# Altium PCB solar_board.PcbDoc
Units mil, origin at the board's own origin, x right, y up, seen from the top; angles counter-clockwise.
Board outline 7810 x 5890 mil, 2 copper layers (Top Layer, Bottom Layer); 87 components, 116 nets, 371 pads, 113 vias.
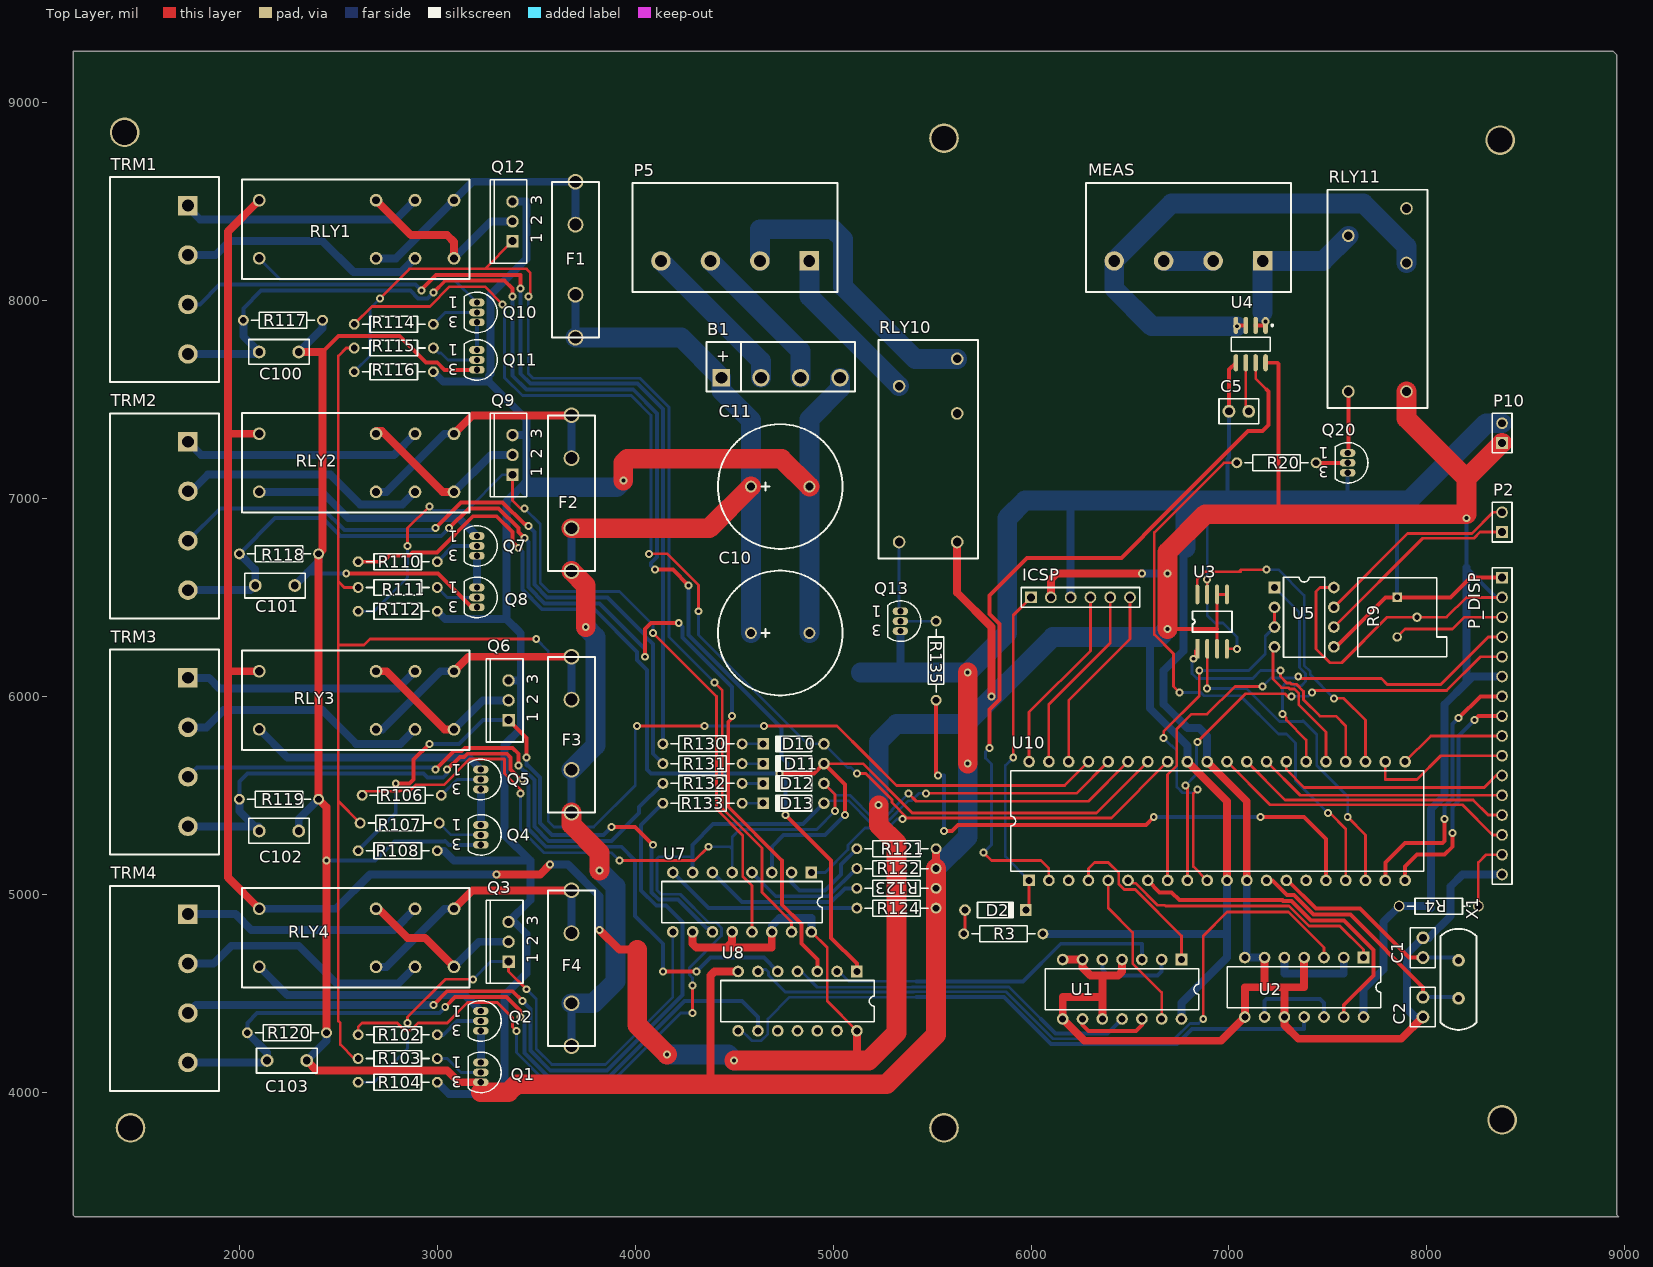
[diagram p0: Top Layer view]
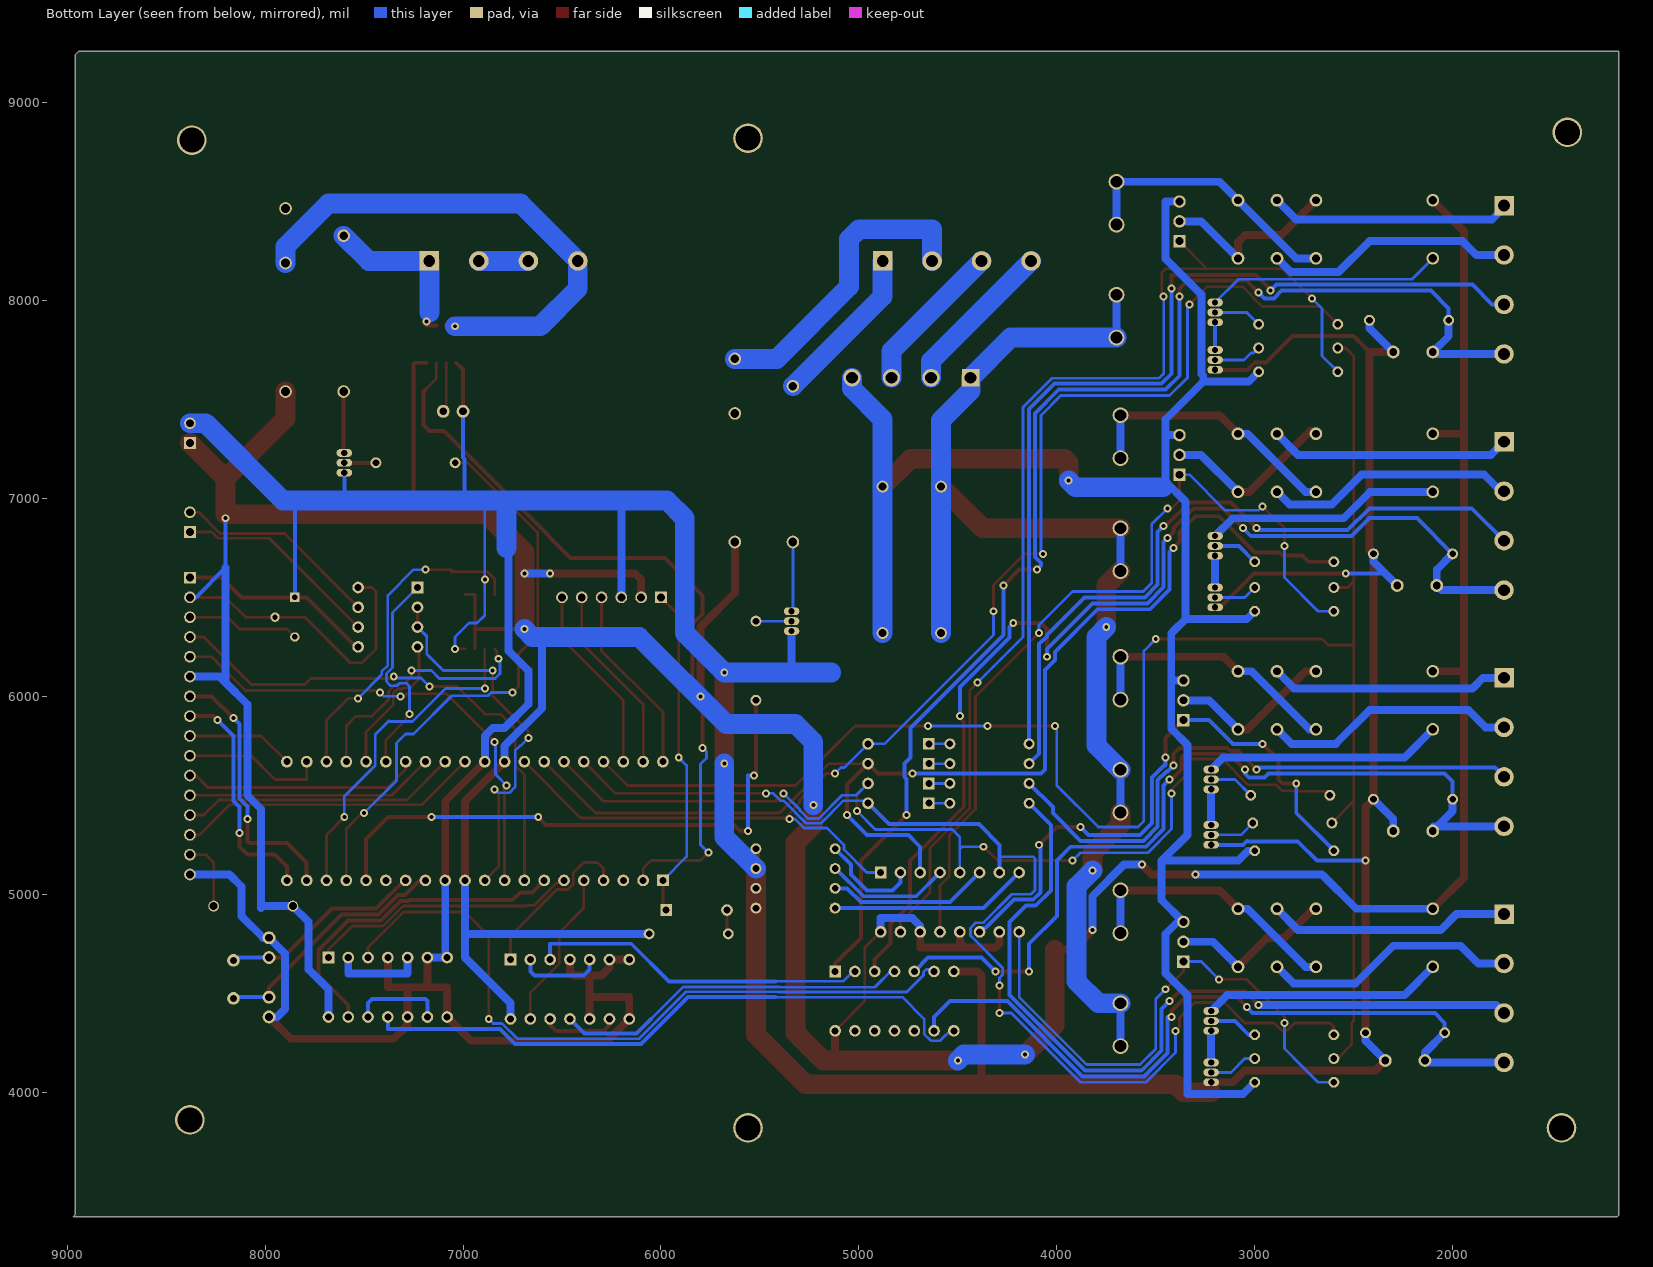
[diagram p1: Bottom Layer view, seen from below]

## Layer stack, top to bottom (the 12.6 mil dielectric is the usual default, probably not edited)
Top Layer: signal copper 1.4
Dielectric: dielectric 12.6, FR-4, Dk 4.8
Bottom Layer: signal copper 1.4

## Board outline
1160,3490 1160,9260 8940,9260 8960,9240 8960,3380 8970,3370 1170,3370 1160,3380

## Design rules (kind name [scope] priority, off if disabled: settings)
Clearance [All] p1: gap=10
ComponentClearance [All] p1: gap=10 collisioncheckmode=3 verticalgap=10
PolygonConnect [All] p1: connectstyle=Relief reliefconductorwidth=10 reliefentries=4 polygonreliefangle="90 Angle"
RoutingCorners [All] p1: cornerstyle=45-Degree minsetback=20 maxsetback=20
RoutingPriority [InNet('GND')] p1: routingpriority=0
RoutingVias [All] p1: holewidth=20 width=40 viastyle="Through Hole" minholewidth=20 minwidth=40 maxholewidth=20 maxwidth=40
SolderMaskExpansion [All] p1: expansion=4
TestPointUsage [All] p1: valid=0 allowmultiple=FALSE
Testpoint [All] p1: side=3 testpointundercomponent=TRUE minsize=40 maxsize=100 preferedsize=60 minholesize=0 maxholesize=40 preferedholesize=32 testpointgrid=1 style=297 order=0123456789
Width [All] p1: maxlimit=100 minlimit=10 preferedwidth=14
16 further rules are at their usual default settings.

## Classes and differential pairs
component class MTR_DRV1: B1 C10 C11 C100 C101 C102 C103 D10 D11 D12 D13 F1 F2 F3 F4 P5 Q1 Q2 Q3 Q4 Q5 Q6 Q7 Q8 Q9 Q10 Q11 Q12 Q13 R102 R103 R104 R106 R107 R108 R110 R111 R112 R114 R115 R116 R117 R118 R119 R120 R121 R122 R123 R124 R130 R131 R132 R133 R135 RLY1 RLY2 RLY3 RLY4 RLY10 TRM1 TRM2 TRM3 TRM4 U7 »»»
component class main: C1 C2 C5 D2 ICSP MEAS P2 P10 P_DISP Q20 R3 R4 R9 R20 RLY9 RLY11 U3 U4 U5 U10 U? X1
component class "Sensor frontend": U1 U2 U8

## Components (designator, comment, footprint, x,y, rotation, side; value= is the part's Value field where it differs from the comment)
B1 "BRIDGE" BRIDGE 4360,7540 r0 top
C1 "Cap" VP32-3.2 7980,4730 r270 top
C2 "Cap" VP32-3.2 7980,4430 r90 top
C5 "Cap" VP32-3.2 7050,7440 r0 top
C10 "Cap Pol1" Capacitor2200u50v 4880,6320 r180 top
C11 "Cap Pol1" Capacitor2200u50v 4880,7060 r180 top
C100 "Cap" VP45-3.2 2200,7740 r180 top
C101 "Cap" VP45-3.2 2180,6560 r180 top
C102 "Cap" VP45-3.2 2200,5320 r180 top
C103 "Cap" VP45-3.2 2240,4160 r180 top
D2 "Diode 1N4150" DO-35A 5820,4920 r0 top
D10 "Diode 1N4150" DO-35A 4800,5760 r180 top
D11 "Diode 1N4150" DO-35A 4800,5660 r180 top
D12 "Diode 1N4150" DO-35A 4800,5560 r180 top
D13 "Diode 1N4150" DO-35A 4800,5460 r180 top
F1 "Fuse5mm" Fuse5mm 3580,8600 r270 top
F2 "Fuse5mm" Fuse5mm 3560,7420 r270 top
F3 "Fuse5mm" Fuse5mm 3560,6200 r270 top
F4 "Fuse5mm" Fuse5mm 3560,5020 r270 top
ICSP "Header 6" HDR1X6 6000,6500 r0 top
MEAS "4XTERMINAL" BLK_TERMX4 7170,8200 r180 top
P2 "Header 2" HDR1X2 8380,6830 r90 top
P5 "4XTERMINAL" BLK_TERMX4 4880,8200 r180 top
P10 "Header 2" HDR1X2 8380,7280 r90 top
P_DISP "Header 16" HDR1X16 8380,6600 r270 top
Q1 "P2N2222A" 29-04 3220,4100 r180 top
Q2 "P2N2222A" 29-04 3220,4360 r180 top
Q3 "IRF3205" TO-220AB 3360,4760 r90 top
Q4 "P2N2222A" 29-04 3220,5300 r180 top
Q5 "P2N2222A" 29-04 3220,5580 r180 top
Q6 "IRF3205" TO-220AB 3360,5980 r90 top
Q7 "P2N2222A" 29-04 3200,6760 r180 top
Q8 "P2N2222A" 29-04 3200,6500 r180 top
Q9 "IRF3205" TO-220AB 3380,7220 r90 top
Q10 "P2N2222A" 29-04 3200,7940 r180 top
Q11 "P2N2222A" 29-04 3200,7700 r180 top
Q12 "IRF3205" TO-220AB 3380,8400 r90 top
Q13 "P2N2222A" 29-04 5340,6380 r180 top
Q20 "P2N2222A" 29-04 7600,7180 r180 top
R3 "Res1" AXIAL-0.4#1 5860,4800 r0 top
R4 "Res1" AXIAL-0.4#2 8060,4940 r180 top
R9 "Res Tap" VR4 7900,6400 r270 top
R20 "Res1" AXIAL-0.4#1 7240,7180 r180 top
R102 "Res1" AXIAL-0.4#1 2800,4290 r180 top
R103 "Res1" AXIAL-0.4#1 2800,4170 r180 top
R104 "Res1" AXIAL-0.4#1 2800,4050 r180 top
R106 "Res1" AXIAL-0.4#1 2820,5500 r180 top
R107 "Res1" AXIAL-0.4#1 2810,5360 r180 top
R108 "Res1" AXIAL-0.4#1 2800,5220 r180 top
R110 "Res1" AXIAL-0.4#1 2800,6680 r180 top
R111 "Res1" AXIAL-0.4#1 2800,6550 r180 top
R112 "Res1" AXIAL-0.4#1 2800,6430 r180 top
R114 "Res1" AXIAL-0.4#1 2780,7880 r180 top
R115 "Res1" AXIAL-0.4#1 2780,7760 r180 top
R116 "Res1" AXIAL-0.4#1 2780,7640 r180 top
R117 "Res1" AXIAL-0.4#1 2220,7900 r180 top
R118 "Res1" AXIAL-0.4#1 2200,6720 r180 top
R119 "Res1" AXIAL-0.4#1 2200,5480 r180 top
R120 "Res1" AXIAL-0.4#1 2240,4300 r180 top
R121 "Res1" AXIAL-0.4#1 5320,5230 r180 top
R122 "Res1" AXIAL-0.4#1 5320,5130 r180 top
R123 "Res1" AXIAL-0.4#1 5320,5030 r180 top
R124 "Res1" AXIAL-0.4#1 5320,4930 r180 top
R130 "Res1" AXIAL-0.4#1 4340,5760 r180 top
R131 "Res1" AXIAL-0.4#1 4340,5660 r180 top
R132 "Res1" AXIAL-0.4#1 4340,5560 r180 top
R133 "Res1" AXIAL-0.4#1 4340,5460 r180 top
R135 "Res1" AXIAL-0.4#1 5520,6180 r90 top
RLY1 "RELAY2" DPDT_Relay 2100,8360 r180 top
RLY2 "RELAY2" DPDT_Relay 2100,7180 r180 top
RLY3 "RELAY2" DPDT_Relay 2100,5980 r180 top
RLY4 "RELAY2" DPDT_Relay 2100,4780 r180 top
RLY10 "RELAY1" SPDT 5480,6780 r270 top
RLY11 "RELAY1" SPDT 7750,7540 r270 top
TRM1 "4XTERMINAL" BLK_TERMX4 1740,8480 r270 top
TRM2 "4XTERMINAL" BLK_TERMX4 1740,7286.67 r270 top
TRM3 "4XTERMINAL" BLK_TERMX4 1740,6093.33 r270 top
TRM4 "4XTERMINAL" BLK_TERMX4 1740,4900 r270 top
U1 "CD4013BCN" N14A 6460,4520 r180 top
U2 "CD4013BCN" N14A 7380,4530 r180 top
U3 "AT45DB161" SOP8 6840,6240 r90 top
U4 "ACS712" 751-05_N 7110,7780 r270 top
U5 "MAX485EPA" PA8 7380,6400 r270 top
U7 "ILD74" J016D 4540,4960 r180 top
U8 "MC74HC14AN" 646-06 4820,4460 r180 top
U10 "PIC18F458-E/P" PDIP600-40 6940,5370 r0 top
X1 "XTAL" XTAL 8160,4570 r90 top

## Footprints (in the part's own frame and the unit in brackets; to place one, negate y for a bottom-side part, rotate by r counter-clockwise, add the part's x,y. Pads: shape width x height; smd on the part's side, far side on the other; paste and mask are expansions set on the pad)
29-04 [mm] "TO, Flat Index; 3 In-Line, Axial Leads; Body Dia. 4.8mm; Leads 0.48 x 0.5 mm (max)"
  oval 2x1 hole 0.8: 1(0,-1.27) 2(0,0) 3(0,1.27)
  silkscreen extent -2.6,-2.6 1.6,2.6
646-06 [mm] "DIP; 14 Leads; Row Spacing 7.62 mm; Pitch 2.54 mm"
  rect 1.5x1.5 hole 0.9: 1(-7.62,-3.81)
  round 1.5 hole 0.9: 2(-5.08,-3.81) 3(-2.54,-3.81) 4(0,-3.81) 5(2.54,-3.81) 6(5.08,-3.81) 7(7.62,-3.81) 8(7.62,3.81) 9(5.08,3.81) 10(2.54,3.81) 11(0,3.81) 12(-2.54,3.81) 13(-5.08,3.81) 14(-7.62,3.81)
  silkscreen extent -9.85,-2.65 9.85,2.65
751-05_N [mm] "SOIC, 8-Leads, Body 4.9x3.9mm, Pitch 1.27mm, IPC Medium Density"
  oval 2.2x0.6 smd: 1(-2.4,1.905) 2(-2.4,0.635) 3(-2.4,-0.635) 4(-2.4,-1.905) 5(2.4,-1.905) 6(2.4,-0.635) 7(2.4,0.635) 8(2.4,1.905)
  silkscreen extent -2.52,-2.5 0.9,2.88, body extent -2,-2.5 2,2.5, height 1.75
AXIAL-0.4#1 [mm] "Resistor; 2 Leads"
  round 1.4 hole 0.85: 1(-5.08,0) 2(5.08,0)
  silkscreen extent -4.06,-1.02 4.06,1.02
AXIAL-0.4#2 [mm] "Resistor; 2 Leads"
  round 1.4 hole 1.016: 1(-5.08,0) 2(5.08,0)
  silkscreen extent -4.06,-1.02 4.06,1.02
BLK_TERMX4 [mm] "4 PIN BLOCK TERMINCAL (6.35MM PITCH)"
  rect 2.5x2.5 hole 1.5: 0(0,0)
  round 2.5 hole 1.5: 1(6.35,0) 2(12.7,0) 3(19.05,0)
  silkscreen extent -3.63,-10 22.68,4
BRIDGE [mil] "KBL401"
  rect 88x88 hole 60: 1(75,70)
  round 88 hole 60: 2(275,70) 3(475,70) 4(675,70)
  silkscreen extent 0,0 750,250
Capacitor2200u50v [mil]
  round 60 hole 40: 1(295.28,0) 2(0,0)
  silkscreen extent -167,-315 463,315
DO-35A [mm] "Diode, Axial; Body 4.6 x 1.9 mm (LxDia. max), Lead Dia. 0.53 mm (max)"
  round 1.5 hole 0.9: 1(-3.9,0)
  rect 1.5x1.5 hole 0.9: 2(3.9,0)
  silkscreen extent -2.3,-1 2.4,1
DPDT_Relay [mm]
  round 1.626 hole 1.016: 1(-25,3.725) 2(-20,3.725) 3(-15,3.725) 6(-15,-3.725) 7(-20,-3.725) 8(-25,-3.725)
  round 1.626 hole 1.118: 4(0,3.725) 5(0,-3.725)
  silkscreen extent -27,-6.4 2.2,6.4
Fuse5mm [mil]
  round 80 hole 60: 1(0,118.11) 2(216.54,118.11) 3(570.87,118.11) 4(787.4,118.11)
  silkscreen extent 0,0 787,236
HDR1X2 [mm] "Connector; Header; 2 Position"
  rect 1.5x1.5 hole 1.016: 1(0,0)
  round 1.5 hole 1.016: 2(2.54,0)
  silkscreen extent -1.27,-1.27 3.81,1.27
HDR1X6 [mm] "Connector; Header; 6 Position"
  rect 1.5x1.5 hole 1.016: 1(0,0)
  round 1.5 hole 1.016: 2(2.54,0) 3(5.08,0) 4(7.62,0) 5(10.16,0) 6(12.7,0)
  silkscreen extent -1.27,-1.27 13.97,1.27
HDR1X16 [mm] "Connector; Header; 16 Position"
  rect 1.5x1.5 hole 1.016: 1(0,0)
  round 1.5 hole 1.016: 2(2.54,0) 3(5.08,0) 4(7.62,0) 5(10.16,0) 6(12.7,0) 7(15.24,0) 8(17.78,0) 9(20.32,0) 10(22.86,0) 11(25.4,0) 12(27.94,0) 13(30.48,0) 14(33.02,0) 15(35.56,0) 16(38.1,0)
  silkscreen extent -1.27,-1.27 39.37,1.27
J016D [mm] "DIP; 16 Leads; Row Spacing 7.62 mm; Pitch 2.54 mm"
  rect 1.5x1.5 hole 0.9: 1(-8.89,-3.81)
  round 1.5 hole 0.9: 2(-6.35,-3.81) 3(-3.81,-3.81) 4(-1.27,-3.81) 5(1.27,-3.81) 6(3.81,-3.81) 7(6.35,-3.81) 8(8.89,-3.81) 9(8.89,3.81) 10(6.35,3.81) 11(3.81,3.81) 12(1.27,3.81) 13(-1.27,3.81) 14(-3.81,3.81) 15(-6.35,3.81) 16(-8.89,3.81)
  silkscreen extent -10.3,-2.65 10.3,2.65
N14A [mm] "DIP; 14 Leads; Row Spacing 7.62 mm; Pitch 2.54 mm"
  rect 1.5x1.5 hole 0.9: 1(-7.62,-3.81)
  round 1.5 hole 0.9: 2(-5.08,-3.81) 3(-2.54,-3.81) 4(0,-3.81) 5(2.54,-3.81) 6(5.08,-3.81) 7(7.62,-3.81) 8(7.62,3.81) 9(5.08,3.81) 10(2.54,3.81) 11(0,3.81) 12(-2.54,3.81) 13(-5.08,3.81) 14(-7.62,3.81)
  silkscreen extent -9.85,-2.65 9.85,2.65
PA8 [mm] "DIP; 8 Leads; Row Spacing 7.62 mm; Pitch 2.54 mm"
  rect 1.5x1.5 hole 0.9: 1(-3.81,-3.81)
  round 1.5 hole 0.9: 2(-1.27,-3.81) 3(1.27,-3.81) 4(3.81,-3.81) 5(3.81,3.81) 6(1.27,3.81) 7(-1.27,3.81) 8(-3.81,3.81)
  silkscreen extent -5.15,-2.65 5.15,2.65
PDIP600-40 [mm] "DIP, Plastic; 40 Leads; Row Spacing 15.24 mm; Pitch 2.54 mm"
  rect 1.5x1.5 hole 0.9: 1(-24.13,-7.62)
  round 1.5 hole 0.9: 2(-21.59,-7.62) 3(-19.05,-7.62) 4(-16.51,-7.62) 5(-13.97,-7.62) 6(-11.43,-7.62) 7(-8.89,-7.62) 8(-6.35,-7.62) 9(-3.81,-7.62) 10(-1.27,-7.62) 11(1.27,-7.62) 12(3.81,-7.62) 13(6.35,-7.62) 14(8.89,-7.62) 15(11.43,-7.62) 16(13.97,-7.62) 17(16.51,-7.62) 18(19.05,-7.62) 19(21.59,-7.62) 20(24.13,-7.62) 21(24.13,7.62) 22(21.59,7.62) 23(19.05,7.62) 24(16.51,7.62) 25(13.97,7.62) 26(11.43,7.62) 27(8.89,7.62) 28(6.35,7.62) 29(3.81,7.62) 30(1.27,7.62) 31(-1.27,7.62) 32(-3.81,7.62) 33(-6.35,7.62) 34(-8.89,7.62) 35(-11.43,7.62) 36(-13.97,7.62) 37(-16.51,7.62) 38(-19.05,7.62) 39(-21.59,7.62) 40(-24.13,7.62)
  silkscreen extent -26.5,-6.45 26.5,6.45
SOP8 [mil]
  rect 100x20 smd: 1(0,0)
  oval 100x20 smd: 2(0,-50) 3(0,-100) 4(0,-150) 5(275,-150) 6(275,-100) 7(275,-50) 8(275,0)
  silkscreen extent 85,-175 190,25
SPDT [mm] "1 From C relay"
  round 1.626 hole 1.118: 1(-20,-3.725) 2(0,3.725) 3(-23.5,3.725) 4(-16.5,3.725) 5(0,-3.725)
  silkscreen extent -25.9,-6.4 2.1,6.4
TO-220AB [mm] "TO, Thru-Hole, Vertical, Heatsink Mounted; 3 In-Line Leads; Pitch 2.54 mm"
  rect 1.6x1.6 hole 1: 1(-2.54,0)
  round 1.6 hole 1: 2(0,0) 3(2.54,0)
  silkscreen extent -5.35,-1.85 5.35,2.85
VP32-3.2 [mm] "Capacitor, Ceramic, Thru-Hole, Dipped Radial; Body 5.1 x 3.2 mm (WxT) Pin Spacing 2.54 mm (typ)"
  round 1.65 hole 1: 1(-1.27,0) 2(1.27,0)
  silkscreen extent -2.55,-1.6 2.55,1.6
VP45-3.2 [mm] "Capacitor, Ceramic, Thru-Hole, Dipped Radial; Body 7.8 x 3.2 mm (WxT) Pin Spacing 5.08 mm (typ)"
  round 1.65 hole 1: 1(-2.54,0) 2(2.54,0)
  silkscreen extent -3.9,-1.6 3.9,1.6
VR4 [mm] "Feed-Through Capacitor; 3 Leads"
  rect 1.2x1.2 hole 0.7: 1(-2.54,-1.27)
  round 1.2 hole 0.7: 2(0,1.27) 3(2.54,-1.27)
  silkscreen extent -5.08,-6.35 5.08,5.08
XTAL [mil]
  round 64.02 hole 35.98: 0(-96.06,0) 1(96.06,0)
  silkscreen extent -255,-92 255,92

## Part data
C1 C2 C5 C100 C101 C102 C103: "Capacitor"
C10 C11: "Polarized Capacitor (Radial)"
D2 D10 D11 D12 D13: "High Conductance Ultra Fast Diode"
ICSP: "Header, 6-Pin"
P2 P10: "Header, 2-Pin"
P_DISP: "Header, 16-Pin"
Q1 Q2 Q4 Q5 Q7 Q8 Q10 Q11 Q13 Q20: "Amplifier Transistor NPN Silicon"
Q3 Q6 Q9 Q12: "HEXFET Power MOSFET"
R3 R4 R20 R102 R103 R104 R106 R107 R108 R110 R111 R112 R114 R115 R116 R117 R118 R119 R120 R121 R122 R123 R124 R130 R131 R132 R133 R135: "Resistor"
R9: "Tapped Resistor"
U1 U2: "Dual D-Type Flip-Flop"
U5: "Low-Power, Slew-Rate-Limited RS-485/RS-422 Transceiver"
U7: "Optocoupler, Phototransistor Output, Dual Channel, TTL Compatible, Pb-free"
U8: "Hex Schmitt Trigger Inverter"
U10: "High Performance, Enhanced FLASH Microcontroller with CAN, 32K FLASH, 40-Pin PDIP, Standard Volt Range, Extended Temperature"

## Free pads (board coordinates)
  round 149.61 hole 125.98: 0(8380,3860) 1(8370,8810) 2(5560,8820) 3(5560,3820) 4(1450,3820) 5(1420,8850)

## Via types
v1: diameter 40, hole 20, Top Layer to Bottom Layer, 113 vias

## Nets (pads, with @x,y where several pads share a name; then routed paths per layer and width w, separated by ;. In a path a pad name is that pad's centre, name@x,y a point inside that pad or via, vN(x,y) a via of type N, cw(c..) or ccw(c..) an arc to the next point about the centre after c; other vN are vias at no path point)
GND: C1.1 C2.1 C5.1 C100.1 C101.1 C102.1 C103.1 ICSP.3 P10.2 P_DISP.1 P_DISP.16 Q1.3 Q4.3 Q8.3 Q11.3 Q13.3 Q20.3 R9.1 R117.1 R118.1 R119.1 R120.1 R121.1 R122.1 R123.1 R124.1 U1.4 U1.6 U1.7 U1.8 U1.10 U2.4 U2.6 U2.7 U2.8 U2.10 U3.4 U3.7 U4.5 U5.5 U8.7 U10.12 U10.31 | length 28897
  Top Layer w14: U3.7 v1(6890,6590) ; U3.4 v1(7040,6240)
  Top Layer w20: C103.1 2377.56,4122.44 ; 2420,7740 2500,7820 2810,7820 2942.44,7687.56 2999.7,7687.56 3037.26,7650 Q11.3 ; v1(2540,6620) 3004.19,6620 3174.19,6450 Q8.3 ; C5.1 7000,7650.51 U4.5 ; U5.5 7540,6250 7790,6500 R9.1 8120,6500 8220,6600 P_DISP.1
  Top Layer w40: C100.1 2420,7740 2420,6740 R118.1 R119.1 2440,5440 R120.1 ; C103.1 2390,4110 3050,4110 3110,4050 Q1.3 ; 4380,4040 4380,4590 4400,4610 U8.7 ; R124.1 R123.1 R122.1 R121.1 ; U1.7 U1.6 6260,4630 6300,4590 6360,4590 ; U1.10 6360,4480 ; U1.4 6460,4610 6440,4590 6360,4590 ; U10.31 7090,5470 U10.12 ; U2.6 7180,4530 ; U2.4 7380,4530 7280,4530 ; v1(7980,4380) 7870,4270 7350,4270 7280,4340 U2.10 7280,4530 ; 6360,4480 6160,4480 U1.8 6270,4260 6960,4260 U2.8 7080,4530 7180,4530 ; 6360,4480 6360,4590 ; 7180,4530 7280,4530
  Top Layer w100: 3220,4000 3360,4000 3400,4040 4380,4040 5270,4040 5520,4290 R124.1 R123.1 R122.1 ; v1(5680,5660) v1(5680,6120)
  Bottom Layer w14: 6880,6990 6890,6980 v1(6890,6590) 6890,6410 6930,6370 6970,6370 7040,6300 v1(7040,6240)
  Bottom Layer w20: 2345.15,6625.15 2350.31,6620 v1(2540,6620) ; v1(2440,5170) 2684.88,5170 2782.44,5267.56 3037.56,5267.56 3040,5270 3060,5250 Q4.3 ; C5.1 7000,7207.26 6992.44,7199.7 6992.44,7007.56 7010,6990 ; 7600,6990 Q20.3 ; R9.1 7850,6990
  Bottom Layer w40: C101.1 2345.15,6625.15 2400,6680 R118.1 ; C102.1 2300,5380 R119.1 ; C100.1 2420,7860 R117.1 ; C103.1 2440,4260 R120.1 ; Q11.3@3199.68,7650.31 Q11.3 ; 5340,6120 Q13.3 ; ICSP.3 6200,6990 ; 6780,6750 6770,6740 6770,6230 6670,6130 6670,5960 6790,5840 6850,5840 6890,5800 U10.31 ; U10.12 7090,4690 U2.7 U2.6 ; v1(7980,4380) 7940,4380 7900,4420 7900,4700 C1.1 8010,4780 8120,4890 8120,5040 8180,5100 P_DISP.16
  Bottom Layer w100: 5140,6120 5340,6120 v1(5680,6120) 5880,6320 5880,6900 5970,6990 6200,6990 6780,6990 ; R122.1 5680,5290 v1(5680,5660) ; 6780,6750 6780,6990 ; P10.2 8300,7380 7910,6990 7850,6990 7600,6990 7010,6990 6880,6990 6780,6990
HVGND: B1.4 C10.2 C11.2 Q3.3 Q6.3 Q9.3 Q12.3 R104.1 R108.1 R112.1 R116.1 | length 9740.4
  Top Layer w100: v1(3940,7090) 3940,7180 3960,7200 4740,7200 C11.2
  Bottom Layer w40: R116.1 3030,7590 3260,7590 ; R104.1 3060,3990 3340,3990 3340,4490 3450,4600 3450,4800 3391.5,4858.5 3358.5,4858.5 Q3.3 3470,4970 3470,5170 ; R108.1 3033.43,5220 3083.43,5170 3470,5170 ; R112.1 3040,6390 3350,6390 ; Q6.3 3420,6080 ; Q9.3 3450,7320 ; Q12.3 3450,8500 3450,8210 3269.37,8029.37 3269.37,7629.42 3260,7620.05 3260,7590 ; 3415,6325 3350,6390 ; 3450,7330 3450,7320 ; 3260,7590 3450,7400 3450,7320 ; 3350,6390 3350,6984.58 3450,7084.58 3450,7320 ; 3350,6390 3421.5,6318.5 3421.5,5836.08 3340,5754.58 3340,5300 3470,5170
  Bottom Layer w100: 3463.92,7056.08 3906.08,7056.08 v1(3940,7090) ; C10.2 C11.2 4880,7400 5035,7555 B1.4
NetB1_2: B1.2 P5.3 | length 799.2
  Bottom Layer w100: P5.3 4635,7695 B1.2
NetB1_3: B1.3 P5.2 | length 778.5
  Bottom Layer w100: P5.2 4835,7745 B1.3
NetC1_2: C1.2 U10.14 X1.1 | length 1037.3
  Top Layer w20: U10.14 7296.98,5070 7439.98,4927 7663,4927 7910,4680 C1.2
  Bottom Layer w20: C1.2 8146.06,4680 X1.1
NetC2_2: C2.2 U10.13 X1.0 | length 1246.2
  Top Layer w20: U10.13 7219.96,5070 7292.96,4997 7327.55,4997 7427.55,4897 7613,4897 7980,4530 C2.2
  Bottom Layer w20: C2.2 8153.94,4480 X1.0
NetC5_2: C5.2 U4.6 | length 251.7
  Top Layer w14: U4.6 7085,7455 C5.2
NetC100_2: C100.2 R117.2 TRM1.3 U8.1 | length 6657.8
  Top Layer w20: v1(2980,8040) 3040,8100 3339.92,8100 3380,8059.92 v1(3380,8020) ; v1(4100,6640) 4190,6640 v1(4270,6560) ; v1(4760,5400) 4990,5170 4990,4780 5120,4650 U8.1
  Bottom Layer w20: R117.2 2020,7960 2110,8050 2863.43,8050 2903.43,8010 2950,8010 v1(2980,8040) ; v1(3380,8020) 3380,7620 3450,7550 3990,7550 4110,7430 4110,6703.43 4080,6673.43 4080,6660 v1(4100,6640) ; v1(4270,6560) 4270,6310 4740,5840 4740,5690 4770,5660 4770,5593.43 4760,5583.43 v1(4760,5400)
  Bottom Layer w40: TRM1.3 2090,7730 C100.2 2020,7820 R117.2
NetC101_2: C101.2 R118.2 TRM2.3 U8.3 | length 5630.7
  Top Layer w20: v1(3060,6850) 3160,6950 3310,6950 3410,6850 3410,6830 v1(3440,6800) ; v1(4050,6200) 4050,6340 4080,6370 v1(4220,6370) ; v1(4490,5900) 4490,5890 4470,5870 4470,5442.12 4740.47,5171.65 4740.47,4949.1 4839.53,4850.04 4839.53,4750.47 4920,4670 U8.3
  Bottom Layer w20: R118.2 2180,6900 2420,6900 2510,6810 3020,6810 v1(3060,6850) ; v1(3440,6800) 3460,6780 3460,6552.43 3542.43,6470 3820,6470 4050,6240 v1(4050,6200) ; v1(4220,6370) 4240,6350 4240,6297.57 4490,6047.57 v1(4490,5900)
  Bottom Layer w40: TRM2.3 2056.67,6536.67 C101.2 2080,6640 R118.2
NetC102_2: C102.2 R119.2 TRM3.3 U8.5 | length 4378.7
  Top Layer w20: v1(3050,5630) 3113.68,5693.69 3135.5,5693.69 3151.82,5710 3351.18,5710 3370,5691.18 3370,5630 3420,5580 v1(3430,5580) ; v1(4140,4610) v1(4310,4610)
  Bottom Layer w20: R119.2 2000,5570 2040,5610 2930,5610 2950,5590 3030,5590 3050,5610 v1(3050,5630) ; v1(3430,5580) 3460,5550 3460,5330 3550,5240 3930,5240 4000,5170 4000,4890 4140,4750 v1(4140,4610) ; v1(4310,4610) 4380,4680 4650,4680 U8.5
  Bottom Layer w40: TRM3.3 2076.67,5343.33 ; R119.2 2000,5420 2076.67,5343.33 ; C102.2@2096.67,5343.33 2076.67,5343.33 ; C102.2 2076.67,5343.33
NetC103_2: C103.2 R120.2 TRM4.3 U8.9 | length 3859.7
  Top Layer w20: v1(3040,4430) 3090,4480 3230,4480 ; 3270,4480 3230,4480 ; v1(3420,4380) 3420,4410 3350,4480 3230,4480
  Bottom Layer w20: R120.2 2040,4350 2090,4400 3010,4400 v1(3040,4430) ; v1(3420,4380) 3440,4380 3440,4198.18 3558.18,4080 3870,4080 4250,4460 4540,4460 4620,4380 U8.9
  Bottom Layer w40: TRM4.3 2130,4150 C103.2 2140,4200 R120.2
NetD2_1: D2.1 R3.1 | length 113.5
  Top Layer w14: R3.1@5666.46,4806.46 D2.1
NetD2_2: D2.2 ICSP.1 U10.1 | length 1667.1
  Top Layer w14: v1(5910,5690) 5910,6410 ICSP.1 ; D2.2@5990,4936.46 U10.1
  Bottom Layer w14: v1(5910,5690) 5870,5650 5870,5190 U10.1
NetD10_1: D10.1 R114.2 U7.1 U10.33 | length 6800.8
  Top Layer w14: R114.2 2670,7970 2962.33,7970 3062.33,8070 3240,8070 v1(3330,7980) ; v1(4070,6720) 4162.33,6720 4320,6562.33 v1(4320,6430) ; v1(5120,5610) 5164.75,5610 5297,5477.75 5297,5463 5374,5386 6406,5386 U10.33
  Bottom Layer w14: v1(3330,7980) 3340,7970 3340,7610 3430,7520 3980,7520 4080,7420 4080,6720 v1(4070,6720) ; v1(4320,6430) 4320,6310 4870,5760 D10.1 5073.54,5640 5090,5640 v1(5120,5610) ; U7.1 4960,5110 5075.44,5225.44 5075.44,5248.46 5161.98,5335 5277.63,5335 5322.63,5380 v1(5350,5380)
NetD10_2: D10.2 R130.1 | length 106.5
  Bottom Layer w14: R130.1 D10.2
NetD11_1: D11.1 R110.2 U7.3 U10.34 | length 6185
  Top Layer w14: D11.1 5150,5660 5400,5410 6330,5410 U10.34
  Top Layer w20: R110.2 2728.18,6680 2759.09,6710.91 2857.48,6710.91 2874.13,6727.56 2997.56,6727.56 3180,6910 3300,6910 3380,6830 3380,6780 v1(3410,6750) ; v1(4730,5610) 4903.54,5610 D11.1 5060,5553.54 v1(5060,5400)
  Bottom Layer w20: v1(3410,6750) 3430,6730 3430,6540 3530,6440 3793.43,6440 4010,6223.43 4010,6183.43 4060,6133.43 4060,5630 4079.53,5610.47 4729.53,5610.47 v1(4730,5610) ; U7.3 4690,5240 4750,5300 4960,5300 v1(5060,5400)
NetD11_2: D11.2 R131.1 | length 106.5
  Bottom Layer w14: R131.1 D11.2
NetD12_1: D12.1 R106.2 U7.5 U10.35 | length 5053.2
  Top Layer w14: R106.2 2640,5520 2810,5520 2810,5522.98 2861.18,5523 2891.18,5553 3033,5553 3163,5683 3340,5683 3340,5610 3430,5520 v1(3420,5510) ; v1(3920,5170) 4300,5170 v1(4370,5240) ; D12.1 5010,5503.54 v1(5010,5420) ; v1(5380,5510) 5420,5470 6290,5470 U10.35
  Bottom Layer w14: v1(3420,5510) 3420,5330 3540,5210 3720,5210 ; 3730,5210 3720,5210 ; v1(3920,5170) 3880,5210 3720,5210 ; v1(4370,5240) 4480,5240 4490,5230 ; U7.5 4490,5230 ; D12.1 5013.54,5500 5085.25,5500 5202.25,5383 5257.75,5383 5297,5422.25 5297,5427 v1(5380,5510) ; v1(5010,5420) 4917,5327 4527,5327 4490,5290 4490,5230
NetD12_2: D12.2 R132.1 | length 106.5
  Bottom Layer w14: R132.1 D12.2
NetD13_1: D13.1 R102.2 U7.7 U10.36 | length 5977
  Top Layer w14: R102.2 2600,4330 2620,4350 2797.67,4350 2834.67,4313 2865.33,4313 2902.33,4350 3050,4350 3153,4453 3303,4453 3380,4376 3380,4330 v1(3400,4310) ; v1(4290,4400) v1(4290,4540) ; v1(5470,5510) 6230,5510 U10.36
  Bottom Layer w14: v1(3400,4310) 3400,4200 3550,4050 3880,4050 4230,4400 v1(4290,4400) ; v1(4290,4540) 4290,4577.67 4273,4594.67 4273,4627.2 4436.53,4790.73 4436.53,4829.27 4409.27,4856.53 4370.73,4856.53 4227.26,5000 4130,5000 4110,5020 4110,5180 4120,5190 4290,5190 ; D13.1 4966.54,5473 5078.31,5473 5192.31,5359 5267.69,5359 5381.69,5473 5395.33,5473 5432.33,5510 v1(5470,5510)
  Bottom Layer w20: U7.7 4290,5190 4290,5250 4394,5354 4847.54,5354 D13.1
NetD13_2: D13.2 R133.1 | length 106.5
  Bottom Layer w14: R133.1 D13.2
NetF1_1: F1.1 F1.2 RLY1.3 RLY1.8 | length 1384.3
  Bottom Layer w40: RLY1.3 2790.94,8213.35 RLY1.8 3177.6,8600 F1.1 F1.2
NetF2_1: F2.1 F2.2 RLY2.3 RLY2.8 | length 1364.3
  Top Layer w40: RLY2.8 3177.6,7420 F2.1
  Bottom Layer w40: RLY2.3 2743.35,7033.35 3036.65,7326.65 RLY2.8 ; F2.2 F2.1
NetF3_1: F3.1 F3.2 RLY3.3 RLY3.8 | length 1356
  Top Layer w40: RLY3.8 3157.6,6200 F3.1
  Bottom Layer w40: RLY3.3 2723.35,5833.35 3016.65,6126.65 RLY3.8 ; F3.2 F3.1
NetF4_1: F4.1 F4.2 RLY4.3 RLY4.8 | length 1364.3
  Top Layer w40: RLY4.8 3177.6,5020 F4.1
  Bottom Layer w40: RLY4.3 2743.35,4633.35 3036.65,4926.65 RLY4.8 ; F4.2 F4.1
NetICSP_4: ICSP.4 U10.40 | length 958.4
  Top Layer w14: U10.40 5990,5920 6300,6230 ICSP.4
NetICSP_5: ICSP.5 U10.39 | length 958.4
  Top Layer w14: U10.39 6090,5960 6400,6270 ICSP.5
NetICSP_6: ICSP.6 U10.38 | length 958.4
  Top Layer w14: U10.38 6190,5980 6500,6290 ICSP.6
NetMEAS_0: MEAS.0 RLY11.1 U4.1 U4.2 | length 823.7
  Top Layer w20: U4.2 U4.1 v1(7185,7895)
  Bottom Layer w20: v1(7185,7895) v1@7190,7900
  Bottom Layer w100: 7170,7940 MEAS.0 7475.94,8200 RLY11.1
NetMEAS_1: MEAS.1 MEAS.2 | length 250
  Bottom Layer w100: MEAS.2 MEAS.1
NetMEAS_3: MEAS.3 RLY11.4 U4.3 U4.4 | length 2659
  Top Layer w20: U4.4 U4.3
  Bottom Layer w100: v1(7040,7870) 6610,7870 6420,8060 MEAS.3 6710,8490 7680,8490 7896.65,8273.35 RLY11.4
NetP2_1: P2.1 U5.6 | length 1048.8
  Top Layer w14: U5.6 7979,6799 8237.69,6799 8268.69,6830 P2.1
NetP2_2: P2.2 U5.7 | length 1048.8
  Top Layer w14: U5.7 7903,6823 8227.75,6823 8334.75,6930 P2.2
NetP5_0: P5.0 RLY10.1 | length 820.4
  Bottom Layer w100: P5.0 4880,8020.75 RLY10.1
NetP5_1: P5.1 RLY10.3 | length 1568.5
  Bottom Layer w100: P5.1 4630,8360 5000,8360 5050,8310 5050,8070 5414.8,7705.2 RLY10.3
NetP_DISP_3: P_DISP.3 R9.3 | length 581.4
  Top Layer w14: R9.3 7890,6340 8100,6340 ; 8110,6340 8100,6340 ; P_DISP.3 8190,6400 8130,6340 8100,6340
NetP_DISP_4: P_DISP.4 U10.8 | length 2673.5
  Top Layer w14: U10.8 6690,5604.2 6736.53,5650.73 6736.53,5836.53 ; 6740,5840 6736.53,5836.53 ; v1(7170,6050) 7030,6050 6890,5910 6810,5910 6736.53,5836.53 ; v1(7350,6100) 7350,6090 7770,6090 7800,6060 8070,6060 8310,6300 P_DISP.4
  Bottom Layer w14: v1(7170,6050) 7213,6093 7347,6093 7350,6090 v1(7350,6100)
NetP_DISP_5: P_DISP.5 U10.9 | length 2472
  Top Layer w14: v1(6780,5550) 6790,5550 U10.9 ; v1(6840,5770) 7083,6013 7283,6013 7306,5990 v1(7316,6000) ; v1(7420,6020) 7430,6030 8100,6030 8270,6200 P_DISP.5
  Bottom Layer w14: v1(6780,5550) 6836.53,5606.53 6836.53,5766.53 v1(6840,5770) ; v1(7316,6000) 7400,6000 v1(7420,6020)
NetP_DISP_7: P_DISP.7 U10.19 | length 1350.1
  Top Layer w20: U10.19 7790,5160 7890,5260 8080,5260 8090,5270 v1(8090,5380) ; v1(8160,5890) 8270,6000 P_DISP.7
  Bottom Layer w20: v1(8090,5380) 8090,5443.43 8130,5483.43 8130,5860 v1(8160,5890)
NetP_DISP_8: P_DISP.8 U10.20 | length 1185.3
  Top Layer w20: U10.20 7890,5140 7950,5200 8090,5200 8130,5240 v1(8130,5310) ; v1(8240,5880) 8260,5900 P_DISP.8
  Bottom Layer w20: v1(8130,5310) 8130,5441.01 8160,5471.01 8160,5800 v1(8240,5880)
NetP_DISP_9: P_DISP.9 U10.21 | length 543.8
  Top Layer w14: U10.21 8020,5800 P_DISP.9
NetP_DISP_10: P_DISP.10 U10.22 | length 729.7
  Top Layer w14: U10.22 7790,5580 7950,5580 8070,5700 P_DISP.10
NetP_DISP_11: P_DISP.11 U10.27 | length 1192.1
  Top Layer w14: U10.27 7290,5630 7380,5540 8290,5540 8350,5600 P_DISP.11
NetP_DISP_12: P_DISP.12 U10.28 | length 1260.4
  Top Layer w14: U10.28 7360,5500 P_DISP.12
NetP_DISP_13: P_DISP.13 U10.29 | length 1401.8
  Top Layer w14: U10.29 7284,5476 8234,5476 8310,5400 P_DISP.13
NetP_DISP_14: P_DISP.14 U10.30 | length 1543.3
  Top Layer w14: U10.30 7208,5452 8180,5452 8332,5300 P_DISP.14
NetP_DISP_15: P_DISP.15 R4.1 | length 356.6
  Top Layer w14: R4.1 8260,5160 8300,5200 P_DISP.15
NetQ1_1: Q1.1 Q2.3 | length 160
  Bottom Layer w40: Q1.1 Q2.3
NetQ1_2: Q1.2 R103.1 | length 249
  Bottom Layer w14: R103.1 3050,4170 3120,4100 Q1.2
NetQ2_1: Q2.1 RLY4.4 | length 1212.5
  Bottom Layer w40: RLY4.4 2243.35,4490 3140,4490 Q2.1
NetQ2_2: Q2.2 R102.1 | length 249
  Bottom Layer w20: R102.1 3030,4290 3100,4360 Q2.2
NetQ3_1: Q3.1 R104.2 U7.9 | length 2814.8
  Top Layer w14: v1(2850,4350) 2850,4380 3040,4570 v1(3180,4570) ; Q3.1 3360,4610 v1(3450,4520)
  Bottom Layer w14: R104.2 2680,4050 2758.63,4128.63 ; 2770,4140 2758.63,4128.63 ; v1(2850,4350) 2850,4220 2758.63,4128.63 ; v1(3180,4570) 3270,4660 Q3.1 ; v1(3450,4520) 3500,4470 3500,4218.79 3578.79,4140 3849.39,4140 4190,4480.61 U7.9
NetQ3_2: Q3.2 RLY4.1 RLY4.6 | length 843.4
  Top Layer w40: RLY4.6 2703.35,4926.65 2850,4780 2937.6,4780 RLY4.1
  Bottom Layer w40: RLY4.1 3210.91,4760 Q3.2
NetQ4_1: Q4.1 Q5.3 | length 180
  Bottom Layer w40: Q4.1 Q5.3
NetQ4_2: Q4.2 R107.1 | length 234.9
  Bottom Layer w12: R107.1 3070,5300 Q4.2
NetQ5_1: Q5.1 RLY3.4 | length 1204.2
  Bottom Layer w40: RLY3.4 2243.35,5690 3160,5690 Q5.1
NetQ5_2: Q5.2 R106.1 | length 233.1
  Bottom Layer w14: R106.1 3100,5580 Q5.2
NetQ6_1: Q6.1 R108.2 U7.11 | length 3052.1
  Top Layer w20: v1(2790,5560) 2860,5560 2880,5580 2880,5680 v1(2960,5760) ; Q6.1 3450,5790 v1(3450,5690) ; v1(3880,5340) 4000,5340 v1(4090,5250)
  Bottom Layer w20: R108.2 2790,5410 v1(2790,5560) ; v1(2960,5760) 3110,5760 3230,5880 Q6.1 ; v1(3450,5690) 3450,5652.43 3452.43,5650 3458.99,5650 3520,5588.99 3520,5360 3580,5300 3840,5300 v1(3880,5340) ; v1(4090,5250) 4083,5243 4083,5008.82 4118.82,4973 4216.07,4973 4359.54,4829.53 4370.47,4829.53 U7.11
NetQ6_2: Q6.2 RLY3.1 RLY3.6 | length 851.7
  Top Layer w40: RLY3.6 2743.35,6126.65 3036.65,5833.35 RLY3.1
  Bottom Layer w40: RLY3.1 3230.91,5980 Q6.2
NetQ7_1: Q7.1 RLY2.4 | length 1192.5
  Bottom Layer w40: RLY2.4 2416.65,7033.35 2550,6900 3110,6900 Q7.1
NetQ7_2: Q7.2 R110.1 | length 233.1
  Bottom Layer w20: R110.1 3080,6760 Q7.2
NetQ7_3: Q7.3 Q8.1 | length 160
  Bottom Layer w40: Q8.1 Q7.3
NetQ8_2: Q8.2 R111.1 | length 220.7
  Bottom Layer w14: R111.1 3050,6500 Q8.2
NetQ9_1: Q9.1 R112.2 U7.13 | length 4260.8
  Top Layer w14: v1(2850,6760) 2850,6850 v1(2960,6960) ; Q9.1 3380,6990 3420,6950 v1(3440,6950) ; v1(4090,6320) 4410,6000 4410,5430 4543.47,5296.53 4543.47,5090.73 4590,5044.2 U7.13
  Bottom Layer w14: R112.2 2680,6430 2850,6600 v1(2850,6760) ; v1(2960,6960) 2980,6940 3150,6940 3330,7120 Q9.1 ; v1(3440,6950) 3520,6870 3520,6573.04 3563.04,6530 3920,6530 4090,6360 v1(4090,6320)
NetQ9_2: Q9.2 RLY2.1 RLY2.6 | length 894.3
  Top Layer w40: RLY2.6@2690,7340 2690.55,7340 2720,7340 3026.65,7033.35 RLY2.1
  Bottom Layer w40: RLY2.1 3270.91,7220 Q9.2
NetQ10_1: Q10.1 RLY1.4 | length 1192.5
  Bottom Layer w14: RLY1.4 2206.35,8107 3083,8107 Q10.1
NetQ10_2: Q10.2 R114.1 | length 244.9
  Bottom Layer w14: R114.1 3040,7940 Q10.2
NetQ10_3: Q10.3 Q11.1 | length 140
  Bottom Layer w20: Q11.1 Q10.3
NetQ11_2: Q11.2 R115.1 | length 244.9
  Bottom Layer w14: R115.1 3005.44,7734.56 3019.17,7734.56 3053.73,7700 Q11.2
NetQ12_1: Q12.1 R116.2 U7.15 | length 5674
  Top Layer w14: v1(2710,8010) 2860,8160 3240,8160 ; Q12.1 3240,8160 ; v1(3460,8020) 3470,8030 3470,8140 3450,8160 3240,8160 ; v1(4400,6070) 4440,6030 4440,5433.94 4640,5233.94 4640,5010 4790,4860 U7.15
  Bottom Layer w14: R116.2 2660,7720 2660,7960 v1(2710,8010) ; Q12.1@3360,8300 Q12.1 ; v1(3460,8020) 3460,7630 3483,7607 4023.61,7607 4170,7460.61 4170,6300 v1(4400,6070)
NetQ12_2: Q12.2 RLY1.1 RLY1.6 | length 936.5
  Top Layer w40: RLY1.6 2867.21,8330 3050,8330 3084.25,8295.75 RLY1.1
  Bottom Layer w40: RLY1.1 3270.91,8400 Q12.2
NetQ13_1: Q13.1 RLY10.5 | length 352.8
  Bottom Layer w14: RLY10.5 5333.35,6436.65 Q13.1
NetQ13_2: Q13.2 R135.2 | length 180
  Bottom Layer w14: Q13.2 R135.2
NetQ20_1: Q20.1 RLY11.5 | length 311.4
  Top Layer w20: Q20.1 7603.35,7233.35 RLY11.5
NetQ20_2: Q20.2 R20.1 | length 160
  Top Layer w20: R20.1 Q20.2
NetR20_2: R20.2 U10.17 | length 2920.4
  Top Layer w14: v1(6750,6020) 6720,6050 6720,6215.25 6623,6312.25 6623,6827.75 6782.25,6987 6975.25,7180 R20.2 ; v1(7500,5410) 7510,5410 7590,5330 U10.17
  Bottom Layer w14: v1(6750,6020) 6857.67,6020 6874.67,6003 7057,6003 7250,5810 7290,5810 7336.53,5763.47 7336.53,5573.47 v1(7500,5410)
NetR103_2: R103.2 R107.2 R111.2 R115.2 U10.37 | length 9251.7
  Top Layer w14: R115.2 2540,7760 2500,7720 2500,6580 ; R103.2 2580,4170 2510,4240 2510,4350 2500,4360 2500,5470 ; R111.2 2530,6550 2500,6580 ; R107.2 2500,5470 ; v1(3500,6290) 2660,6290 2630,6260 2500,6260 ; v1(4010,5850) v1(4350,5850) ; v1(4650,5850) 5020,5850 5170,5700 ; 5149.32,5720.68 5170,5700 ; U10.37 6170,5550 5320,5550 5170,5700 ; 2500,5470 2500,6260 ; 2500,6260 2500,6580
  Bottom Layer w14: v1(3500,6290) 3560,6230 3560,5370 3590,5340 3790,5340 4000,5550 4000,5840 v1(4010,5850) ; v1(4350,5850) v1(4650,5850)
NetR121_2: R121.2 U7.2 | length 512.8
  Bottom Layer w20: U7.2 4790,5060 4830,5020 4960,5020 5040,5100 5040,5150 R121.2
NetR122_2: R122.2 U7.4 | length 637.7
  Bottom Layer w20: U7.4 4710,4990 4977.57,4990 5117.57,5130 R122.2
NetR123_2: R123.2 U7.6 | length 821.1
  Bottom Layer w20: U7.6 4540,4960 4990,4960 5060,5030 R123.2
NetR124_2: R124.2 U7.8 | length 1004.6
  Bottom Layer w20: U7.8 4370,4930 R124.2
NetR130_2: R130.2 TRM1.2 | length 4756.8
  Top Layer w20: v1(2920,8050) 2920,8056.57 2993.43,8130 3420,8130 v1(3420,8060)
  Bottom Layer w20: TRM1.2 1800,7980 1900,8080 2890,8080 v1(2920,8050) ; v1(3420,8060) 3420,7630 3470,7580 4012.43,7580 4140,7452.43 R130.2
NetR131_2: R131.2 TRM2.2 | length 3607.2
  Top Layer w20: v1(2990,6850) 3120,6980 3330,6980 3440,6870 3460,6870 v1(3460,6860)
  Bottom Layer w20: TRM2.2 1903.33,6950 2420,6950 2530,6840 2980,6840 v1(2990,6850) ; v1(3460,6860) 3490,6830 3490,6564.85 3554.85,6500 3860,6500 4050,6310 4050,6303.43 4090,6263.43 4090,5710 R131.2
NetR132_2: R132.2 TRM3.2 | length 2973.7
  Top Layer w20: v1(2990,5630) 3083.68,5723.69 3123.07,5723.69 3139.39,5740 3380,5740 3410,5710 v1(3410,5650)
  Bottom Layer w20: TRM3.2 1786.67,5640 2980,5640 v1(2990,5630) ; v1(3410,5650) 3440,5620 3446.57,5620 3490,5576.57 3490,5342.43 3562.43,5270 3880,5270 4020,5410 4020,5440 R132.2
NetR133_2: R133.2 TRM4.2 | length 4121.1
  Top Layer w20: v1(2980,4440) 3050,4510 3380,4510 v1(3430,4460)
  Bottom Layer w20: v1(3430,4460) 3470,4420 3470,4210.61 3570.61,4110 3857.57,4110 4239.53,4491.95 4239.53,4859.53 4156.06,4943 4106.39,4943 4030,5019.39 4030,5350 R133.2
  Bottom Layer w40: TRM4.2 1780,4440 v1(2980,4440)
NetR135_1: R135.1 U10.16 | length 2908.7
  Top Layer w20: R135.1 5520,5610 v1(5530,5600) ; v1(5560,5320) 5600,5320 5630,5350 6580,5350 v1(6620,5390) ; v1(7160,5390) 7380,5390 7490,5280 U10.16
  Bottom Layer w20: v1(5530,5600) 5560,5600 v1(5560,5320) ; v1(6620,5390) v1(7160,5390)
NetRLY1_2: RLY1.2 TRM1.1 | length 1269.7
  Bottom Layer w40: TRM1.1 1880,8230 1950,8300 2420,8300 2576,8144 2818.06,8144 RLY1.2
NetRLY1_7: RLY1.7 TRM1.0 | length 1222.3
  Bottom Layer w40: TRM1.0 1740,8470 1800,8410 2790.75,8410 RLY1.7
NetRLY2_2: RLY2.2 TRM2.1 | length 1270.3
  Bottom Layer w40: TRM2.1 1756.67,7036.67 1840,7120 2460,7120 2610,6970 2824.06,6970 RLY2.2
NetRLY2_7: RLY2.7 TRM2.0 | length 1219.2
  Bottom Layer w40: TRM2.0 1806.67,7220 2780.75,7220 RLY2.7
NetRLY3_2: RLY3.2 TRM3.1 | length 1317.4
  Top Layer w40: TRM3.1 TRM3.1@1743.33,5843.33
  Bottom Layer w40: TRM3.1 TRM3.1@1743.33,5843.33 ; TRM3.1@1743.33,5873.33 TRM3.1@1743.33,5843.33 ; RLY3.2 2814.06,5760 2590,5760 2420,5930 1920,5930 1833.33,5843.33 TRM3.1@1743.33,5843.33
NetRLY3_7: RLY3.7 TRM3.0 | length 1205.4
  Bottom Layer w40: TRM3.0 1846.67,6093.33 1900,6040 2800.75,6040 RLY3.7
NetRLY4_2: RLY4.2 TRM4.1 | length 1297.9
  Bottom Layer w40: TRM4.1 1870,4650 1960,4740 2300,4740 2490,4550 2804.06,4550 RLY4.2
NetRLY4_7: RLY4.7 TRM4.0 | length 1224.7
  Bottom Layer w40: TRM4.0 1980,4900 2060,4820 2780.75,4820 RLY4.7
NetU1_1: U1.1 U10.4 | length 848.4
  Top Layer w14: U10.4 6290,5130 6320,5160 6390,5160 6443.47,5106.53 6443.47,5050.73 6470.73,5023.47 6526.53,5023.47 6760,4790 U1.1
NetU1_2: U1.2 U1.5 | length 430.7
  Bottom Layer w20: U1.5 6360,4620 6390,4590 6640,4590 6660,4610 U1.2
NetU1_3: U1.3 U8.2 | length 1719.4
  Bottom Layer w14: U8.2@5030,4620 5030,4610 5080,4560 5420,4560
  Bottom Layer w20: 5420,4560 5960,4560 6150,4750 6560,4750 U1.3
NetU1_9: U1.9 U1.12 | length 384.9
  Top Layer w20: U1.9 6260,4340 6290,4310 6530,4310 6560,4340 U1.12
NetU1_11: U1.11 U8.4 | length 1794.9
  Bottom Layer w14: U8.4@4830,4620 4920,4530 5397.88,4530 5398.88,4531 5889,4531 6050,4370
  Bottom Layer w20: 6050,4370 6123,4297 6387,4297 U1.11
NetU1_13: U1.13 U10.5 | length 811.8
  Top Layer w14: U10.5 6390,4930 6513.47,4806.53 6513.47,4650.73 6660,4504.2 U1.13
NetU2_1: U2.1 U10.6 | length 1375
  Top Layer w14: U10.6 6503.9,5056.1 6527.84,5056.1 6639.94,4944 6676,4944 6680,4940 7303.94,4940 7403.94,4840 7560,4840 7680,4720 U2.1
NetU2_2: U2.2 U2.5 | length 460
  Bottom Layer w40: U2.5 7280,4600 7580,4600 U2.2
NetU2_3: U2.3 U8.6 | length 3640.7
  Top Layer w14: v1(6870,4370) 6870,4790 6990,4910 7300,4910 7480,4730 U2.3
  Bottom Layer w14: U8.6@4630,4620 4660,4620 4673.47,4606.53 4673.47,4590.73 4758.2,4506 5407.82,4506 5408.82,4507 5874.82,4507 6111.82,4270 6725.8,4270 6802.8,4347 6847,4347 v1(6870,4370)
NetU2_9: U2.9 U2.12 | length 462.4
  Bottom Layer w20: U2.9 7180,4460 7190,4470 7460,4470 7480,4450 U2.12
NetU2_11: U2.11 U8.8 | length 3200.4
  Bottom Layer w14: U8.8@4530,4320 4590,4260 4635.8,4260 4670,4294.2 4670,4370 4780,4480 5420,4480
  Bottom Layer w20: 5420,4480 5863.63,4480 6100.63,4243 6736.98,4243 6813.98,4320 7380,4320 U2.11
NetU2_13: U2.13 U10.7 | length 1685.2
  Top Layer w20: U10.7 6650,5010 6710,5010 6750,4970 7270,4970 7273,4967 7315.12,4967 7415.12,4867 7580.34,4867 7729.53,4717.81 7729.53,4589.53 7580,4440 U2.13
NetU3_1: U3.1 U10.24 | length 1278.6
  Top Layer w14: v1(6820,6190) 6830,6200 6830,6230 U3.1 ; v1(7260,6130) 7260,6100 7292,6068 7309.88,6068 7316.88,6061 7341.27,6061 7377,6025.27 7377,5983 7460,5900 7540,5900 7590,5850 U10.24
  Bottom Layer w14: v1(6820,6190) 6813,6183 6813,6114.67 6837.67,6090 7120,6090 7160,6130 v1(7260,6130)
NetU3_2: U3.2 U10.18 | length 1691.7
  Top Layer w14: v1(6890,6040) U3.2 ; v1(7600,5390) 7690,5300 U10.18
  Bottom Layer w14: v1(6890,6040) 7087.67,6040 7254.67,5873 7370,5873 7373.5,5876.5 7443.47,5806.53 7443.47,5650.73 7600,5494.2 v1(7600,5390)
NetU3_8: U3.8 U10.23 | length 1698.6
  Top Layer w14: U3.8 6840,6592.33 6877.67,6630 7050,6630 ; 7060,6630 7050,6630 ; v1(7190,6640) 7060,6640 7050,6630 ; v1(7530,5990) 7580,5990 7690,5880 U10.23
  Bottom Layer w14: v1(7190,6640) 7250,6640 7380,6510 7380,6156.27 7411,6125.27 7411,6109 v1(7530,5990)
NetU4_7: U4.7 U10.2 | length 3910.5
  Top Layer w14: v1(5760,5210) 5800,5170 6050,5170 6090,5130 U10.2 ; U4.7 7135,7605 7190,7550
  Top Layer w20: v1(5790,5740) 5790,5933.43 5840,5983.43 5840,6366.57 5790,6416.57 5790,6510 5980,6700 6457.06,6700 6680,6922.94 7097.06,7340 7170,7340 7200,7370 7200,7540 7190,7550
  Bottom Layer w14: v1(5760,5210) 5800,5250 5800,5657.67 5770,5687.67 5770,5720 v1(5790,5740)
NetU5_1: U5.1 U10.26 | length 1108.1
  Top Layer w14: v1(7270,5910) 7290,5890 7290,5880 7390,5780 U10.26
  Bottom Layer w14: U5.1 7356,6424 7356,6146.33 7387,6115.33 7387,6074.67 7365.33,6053 7334.67,6053 7321.67,6066 7286,6066 7270,6050 v1(7270,5910)
NetU5_2: U5.2 U5.3 U10.10 | length 1936.1
  Top Layer w14: v1(6670,5790) 6670,5822.33 6850,6002.33 v1(6850,6130) ; v1(6840,5530) 6820,5510 6820,5140 U10.10 ; U5.3 U5.2
  Bottom Layer w14: v1(6670,5790) 6710,5750 6713.06,5750 6736.53,5726.53 6736.53,5541.15 6764.67,5513 6823,5513 v1(6840,5530) ; v1(6850,6130) 7100,6130 7183.47,6213.47 7183.47,6303.47 U5.3
NetU5_4: U5.4 U10.25 | length 727.7
  Top Layer w14: U5.4 7223,6243 7223,6087 7266,6044 7299.94,6044 7306.94,6037 7331.33,6037 7353,6015.33 7353,5957 7490,5820 U10.25
NetU10_3: U10.3
V5: ICSP.2 P10.1 P_DISP.2 P_DISP.6 R3.2 R4.2 R9.2 RLY1.5 RLY2.5 RLY3.5 RLY4.5 RLY10.2 RLY11.2 U1.14 U2.14 U3.3 U3.5 U3.6 U4.8 U5.8 U7.10 U7.12 U7.14 U7.16 U8.14 U10.11 U10.32 | length 26856.6
  Top Layer w14: U7.16 4970,4730 4970,4460 U8.14 ; U3.3 6940,6340 U3.6 U3.5 ; U5.8 7460,6550 7440,6530 7440,6240 7510,6170 7570,6170 7800,6400 R9.2 8100,6400 8200,6500 P_DISP.2
  Top Layer w20: v1(6690,6340) 6940,6340 ; U4.8 7244.49,7685.51 7250,7680 7250,6920
  Top Layer w40: RLY4.5 1942.44,5084.21 1942.44,6120 ; RLY3.5 1949.09,6126.65 1942.44,6120 ; RLY2.5 1945.79,7326.65 1942.44,7330 ; RLY1.5 1942.44,8349.09 1942.44,7330 ; v1(3300,5100) 3520,5100 v1(3570,5150) ; v1(3820,4820) 3920,4720 4010,4720 ; U7.10 4290,4750 4310,4730 4460,4730 ; U7.12 4490,4760 4460,4730 ; U7.14 4690,4730 4460,4730 ; U8.14 5120,4170 5130,4160 ; RLY10.2 5626.65,6523.35 5800,6350 v1(5800,6000) ; ICSP.2 6100,6590 6130,6620 v1(6560,6620) ; U10.32 6990,5470 U10.11 ; 1942.44,6120 1942.44,7330
  Top Layer w100: 4010,4720 4010,4340 v1(4160,4190) ; v1(4500,4160) 5130,4160 5180,4160 5320,4300 5320,5260 5230,5350 v1(5230,5450) ; v1(6690,6340) v1(6690,6620) 6690,6730 6880,6920 7250,6920 8200,6920 8200,7100 ; RLY11.2 7896.65,7403.35 8200,7100 ; P10.1 8200,7100
  Bottom Layer w20: v1(8200,6900) 8200,6650 8350,6500 P_DISP.2
  Bottom Layer w40: RLY4.5 2486.65,4926.65 2660,5100 v1(3300,5100) ; v1(3570,5150) 3660,5150 3820,4990 v1(3820,4820) ; U7.14 4690,4840 4730,4880 4890,4880 U7.16 ; R3.2 6990,4800 ; v1(6560,6620) v1(6690,6620) ; 6600,6300 6600,5940 6790,5750 U10.32 ; U1.14 6760,4450 6990,4680 6990,4800 ; U10.11 6990,4800 ; U2.14 7680,4520 7780,4620 7780,4860 R4.2 8010,4940 8020,4930 8020,5430 8090,5500 8090,5960 8200,6070 ; 8200,6650 8200,6070 ; P_DISP.6 8230,6100 8200,6070
  Bottom Layer w100: v1(4160,4190) 4470,4190 v1(4500,4160) ; v1(5230,5450) 5230,5770 5320,5860 5670,5860 6110,6300 6600,6300 6650,6300 v1(6690,6340)
V36: B1.1 C10.1 C11.1 F1.3 F1.4 F2.3 F2.4 F3.3 F3.4 F4.3 F4.4 | length 6349.7
  Top Layer w100: F3.4 3678.11,5351.89 3820,5210 v1(3820,5120) ; F2.4 3750,6560.71 v1(3750,6350) ; F2.3 4373.86,6849.13 C11.1
  Bottom Layer w40: F4.4 F4.3 ; F3.4 F3.3 ; F2.4 F2.3 ; F1.4 F1.3
  Bottom Layer w100: F4.3 3789.13,4449.13 3900,4560 3900,5040 v1(3820,5120) ; F3.3 3800,5751.02 3800,6300 v1(3750,6350) ; F1.4 4232.4,7812.6 B1.1 4435,7545 4584.72,7395.28 C11.1 C10.1
pads on no net: RLY10.4 RLY11.3 U8.10 U8.11 U8.12 U8.13 U10.15

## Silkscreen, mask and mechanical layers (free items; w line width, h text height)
Mechanical 1:
  lines w10: 1310,3700 8550,3700 8550,8970 1350,8970 1310,8970 1310,3700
